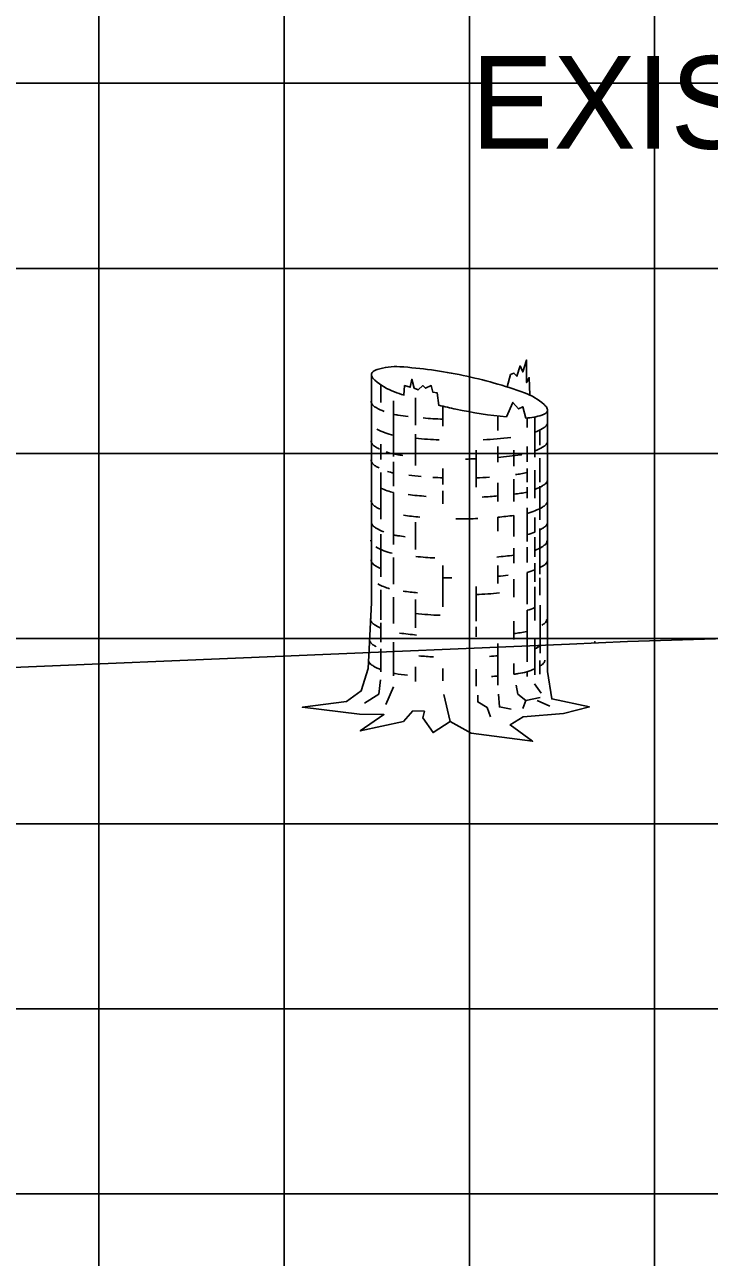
# Model space of a CAD drawing. Extents: x 1147190 to 1147360, y 608981 to 609091.
# Drawn here: x 1147223.54 to 1147227.24, y 609050.99 to 609057.65 of the extents above; entities that cross this region are included whole.
import ezdxf

# ---------------------------------------------------------------- set-up
doc = ezdxf.new("R2010")
doc.units = 0
for name, color, linetype in [('D_Text_Monospaced', 7, 'Continuous'), ('MAJOR', 7, 'Continuous'), ('MINOR', 7, 'Continuous'), ('S_Property_Well_GroundElevation', 7, 'Continuous'), ('S_Roadway_Centerline', 7, 'Continuous'), ('S_Trees_Decid_NonPay', 7, 'Continuous')]:
    doc.layers.add(name, color=color, linetype=linetype)

msp = doc.modelspace()

# ---------------------------------------------------------------- linework, layer by layer
at = {"layer": 'MAJOR'}
msp.add_line((1147202.9409, 609055.3351), (1147342.9409, 609055.3351), dxfattribs=at)
at = {"layer": 'MINOR'}
for p, q in [((1147223.9409, 609045.3351), (1147223.9409, 609065.3351)), ((1147224.9409, 609045.3351), (1147224.9409, 609065.3351)), ((1147225.9409, 609045.3351), (1147225.9409, 609065.3351)), ((1147226.9409, 609045.3351), (1147226.9409, 609065.3351)), ((1147202.9409, 609057.3351), (1147342.9409, 609057.3351)), ((1147202.9409, 609056.3351), (1147342.9409, 609056.3351)), ((1147202.9409, 609054.3351), (1147342.9409, 609054.3351)), ((1147202.9409, 609053.3351), (1147342.9409, 609053.3351)), ((1147202.9409, 609052.3351), (1147342.9409, 609052.3351)), ((1147202.9409, 609051.3351), (1147342.9409, 609051.3351))]:
    msp.add_line(p, q, dxfattribs=at)
at = {"layer": 'S_Property_Well_GroundElevation'}
for p, q in [((1147226.6173, 609054.3165), (1147226.6191, 609054.3183)), ((1147226.6173, 609054.3183), (1147226.6191, 609054.3165)), ((1147226.6182, 609054.3187), (1147226.6182, 609054.3161)), ((1147226.6169, 609054.3174), (1147226.6195, 609054.3174))]:
    msp.add_line(p, q, dxfattribs=at)
at = {"layer": 'S_Roadway_Centerline'}
msp.add_lwpolyline([(1147218.6881, 609053.9767), (1147226.4815, 609054.3046), (1147226.7946, 609054.3184), (1147244.6051, 609054.8887), (1147253.4336, 609054.3345), (1147254.6876, 609054.274), (1147257.845, 609055.0498), (1147258.3829, 609055.1775), (1147258.8229, 609055.1791), (1147261.2905, 609055.1012), (1147268.3857, 609055.2101), (1147272.5872, 609055.2789), (1147275.4381, 609055.2118), (1147283.4827, 609055.1294), (1147286.0369, 609055.041), (1147287.2734, 609054.9959), (1147292.8536, 609054.3763), (1147294.8648, 609054.203), (1147300.0193, 609054.043), (1147301.6888, 609053.9626), (1147303.1605, 609054.01), (1147308.9757, 609054.0188), (1147310.1526, 609054.0695), (1147311.9981, 609054.0658)], dxfattribs=at)
at = {"layer": 'S_Trees_Decid_NonPay'}
for p, q in [((1147225.4633, 609055.7053), (1147225.4633, 609055.6108)), ((1147225.5316, 609055.6186), (1147225.5316, 609055.3181)), ((1147225.6503, 609055.6357), (1147225.6503, 609055.4874)), ((1147225.7973, 609055.5898), (1147225.7973, 609055.4828)), ((1147226.0946, 609055.5373), (1147226.0946, 609055.4585)), ((1147226.252, 609055.5268), (1147226.252, 609055.4749)), ((1147226.2947, 609055.532), (1147226.2947, 609055.3142)), ((1147226.3216, 609055.4618), (1147226.3216, 609055.3798)), ((1147225.4633, 609055.3844), (1147225.4633, 609055.3017)), ((1147225.6503, 609055.4395), (1147225.6503, 609055.2709)), ((1147225.9771, 609055.3536), (1147225.9771, 609055.1534)), ((1147226.0946, 609055.3719), (1147226.0946, 609055.2873)), ((1147226.1812, 609055.3536), (1147226.1812, 609055.2669)), ((1147226.252, 609055.3719), (1147226.252, 609055.2892)), ((1147225.5316, 609055.2892), (1147225.5316, 609055.158)), ((1147225.7973, 609055.2545), (1147225.7973, 609055.1679)), ((1147226.252, 609055.2545), (1147226.252, 609055.1803)), ((1147226.3216, 609055.3102), (1147226.3216, 609055.1803)), ((1147225.4633, 609055.2322), (1147225.4633, 609054.9809)), ((1147226.1812, 609055.1967), (1147226.1812, 609055.0753)), ((1147226.2947, 609055.2453), (1147226.2947, 609055.0937)), ((1147225.5316, 609055.1239), (1147225.5316, 609054.8431)), ((1147225.7973, 609055.1331), (1147225.7973, 609055.0629)), ((1147226.0946, 609055.1764), (1147226.0946, 609055.0753)), ((1147226.252, 609055.1534), (1147226.252, 609055.0937)), ((1147226.3216, 609055.158), (1147226.3216, 609054.9763)), ((1147226.0946, 609054.9907), (1147226.0946, 609054.9146)), ((1147226.1812, 609054.9999), (1147226.1812, 609054.8857)), ((1147226.252, 609055.0406), (1147226.252, 609054.8595)), ((1147226.2947, 609054.9887), (1147226.2947, 609054.9106)), ((1147225.6503, 609054.9644), (1147225.6503, 609054.8162)), ((1147226.3216, 609054.929), (1147226.3216, 609054.6823)), ((1147225.4633, 609054.8982), (1147225.4633, 609054.6679)), ((1147226.2947, 609054.8837), (1147226.2947, 609054.7768)), ((1147226.1812, 609054.824), (1147226.1812, 609054.742)), ((1147226.252, 609054.828), (1147226.252, 609054.7459)), ((1147225.5316, 609054.7728), (1147225.5316, 609054.6285)), ((1147225.7973, 609054.7295), (1147225.7973, 609054.5071)), ((1147226.0946, 609054.7295), (1147226.0946, 609054.6324)), ((1147226.2947, 609054.742), (1147226.2947, 609054.641)), ((1147226.1812, 609054.6554), (1147226.1812, 609054.5583)), ((1147226.252, 609054.6921), (1147226.252, 609054.5215)), ((1147226.3216, 609054.6633), (1147226.3216, 609054.5688)), ((1147225.4633, 609054.5976), (1147225.4633, 609054.4369)), ((1147225.9771, 609054.616), (1147225.9771, 609054.429)), ((1147226.2947, 609054.6154), (1147226.2947, 609054.433)), ((1147225.5316, 609054.5583), (1147225.5316, 609054.4165)), ((1147225.6503, 609054.5465), (1147225.6503, 609054.3936)), ((1147226.252, 609054.4881), (1147226.252, 609054.2085)), ((1147226.3236, 609054.5156), (1147226.3222, 609054.2558)), ((1147225.4633, 609054.4205), (1147225.4633, 609054.3155)), ((1147225.9771, 609054.3982), (1147225.9771, 609054.345)), ((1147226.1812, 609054.429), (1147226.1812, 609054.3299)), ((1147226.2947, 609054.3299), (1147226.2947, 609054.1383)), ((1147225.4633, 609054.2788), (1147225.4633, 609054.1547)), ((1147225.5316, 609054.3155), (1147225.5316, 609054.1344)), ((1147226.0946, 609054.3076), (1147226.0946, 609054.0832)), ((1147226.1812, 609054.2007), (1147226.1812, 609054.1423)), ((1147226.3216, 609054.2171), (1147226.3216, 609054.1429)), ((1147225.6503, 609054.1816), (1147225.6503, 609054.1036)), ((1147225.7973, 609054.1738), (1147225.7973, 609054.1075)), ((1147225.9771, 609054.1692), (1147225.9771, 609054.0786)), ((1147226.252, 609054.156), (1147226.252, 609054.1305)), ((1147225.5309, 609054.0747), (1147225.4896, 609053.9782)), ((1147226.2927, 609054.0911), (1147226.3275, 609054.0399)), ((1147225.8373, 609053.8877), (1147225.8026, 609054.0333)), ((1147226.3747, 609053.9697), (1147226.3072, 609054.0005))]:
    msp.add_line(p, q, dxfattribs=at)
for points in [[(1147226.2678, 609055.6501), (1147226.2638, 609055.7446), (1147226.2494, 609055.7177), (1147226.2494, 609055.8391), (1147226.2284, 609055.7755), (1147226.214, 609055.8083), (1147226.1976, 609055.7525), (1147226.1812, 609055.7696), (1147226.1628, 609055.761), (1147226.1438, 609055.6941)], [(1147226.3629, 609055.5694), (1147226.3629, 609054.1574), (1147226.3852, 609054.0091), (1147226.5886, 609053.9658), (1147226.4489, 609053.9303), (1147226.2304, 609053.912), (1147226.1608, 609053.8686), (1147226.2822, 609053.7801), (1147225.9509, 609053.8234), (1147225.8373, 609053.8877), (1147225.7448, 609053.8273), (1147225.689, 609053.906), (1147225.6976, 609053.9428), (1147225.6359, 609053.9448), (1147225.5841, 609053.8877), (1147225.3518, 609053.8358), (1147225.4791, 609053.9244), (1147225.3472, 609053.9264), (1147225.0388, 609053.9638), (1147225.2776, 609053.9946), (1147225.3557, 609054.0524), (1147225.3944, 609054.1738), (1147225.4115, 609054.5274), (1147225.4115, 609055.761)], [(1147225.7757, 609055.595), (1147225.7671, 609055.662), (1147225.7429, 609055.6665), (1147225.7343, 609055.7013), (1147225.7035, 609055.6869), (1147225.689, 609055.7013), (1147225.6648, 609055.6784), (1147225.6418, 609055.6869), (1147225.6293, 609055.7361), (1147225.6215, 609055.6928), (1147225.5906, 609055.7013), (1147225.5873, 609055.6501)], [(1147226.2455, 609055.5261), (1147226.2284, 609055.5878), (1147226.2061, 609055.576), (1147226.1753, 609055.6108), (1147226.1418, 609055.5327)], [(1147225.4607, 609054.1121), (1147225.4522, 609054.0353), (1147225.3741, 609053.9861)], [(1147226.2448, 609054.0005), (1147226.2015, 609054.0353), (1147226.1936, 609054.0832)], [(1147225.9856, 609054.0294), (1147225.9856, 609053.9927), (1147226.0368, 609053.9618), (1147226.0539, 609053.912)], [(1147226.0972, 609054.0353), (1147226.1031, 609053.9658), (1147226.1667, 609053.9533)], [(1147226.3236, 609054.0169), (1147226.2448, 609054.0005), (1147226.2284, 609053.9572)]]:
    msp.add_lwpolyline(points, dxfattribs=at)
for centre, radius, start, end in [((1147225.4716, 609055.6996), 0.0935, 108.17229, 119.39599), ((1147225.5428, 609055.4827), 0.3218, 86.05435, 108.17229), ((1147225.3924, 609053.3027), 2.507, 78.17229, 86.05435), ((1147225.4297, 609055.7611), 0.0179, 168.17229, 184.22782), ((1147225.4355, 609055.7615), 0.0237, 184.22782, 198.17229), ((1147225.4297, 609055.7611), 0.0179, 152.11676, 168.17229), ((1147225.4449, 609055.7646), 0.0336, 198.17229, 216.94859), ((1147225.4348, 609055.7584), 0.0237, 138.17229, 152.11676), ((1147225.4422, 609055.7518), 0.0336, 119.39599, 138.17229), ((1147225.4927, 609055.8006), 0.0935, 216.9486, 228.17229), ((1147225.645, 609055.9708), 0.3218, 228.17229, 250.29024), ((1147225.3924, 609053.3027), 2.507, 70.29024, 78.17229), ((1147226.382, 609058.0279), 2.507, 250.29024, 251.52809), ((1147226.1294, 609055.3598), 0.3218, 48.17229, 70.29024), ((1147225.4301, 609055.6137), 0.0191, 163.94846, 180), ((1147225.4301, 609055.6137), 0.0191, 180, 196.05154), ((1147225.436, 609055.6154), 0.0252, 196.05154, 210), ((1147225.445, 609055.6206), 0.0356, 210, 228.74941), ((1147225.4864, 609055.6678), 0.0984, 228.74941, 240), ((1147226.382, 609058.0279), 2.507, 255.99867, 258.17229), ((1147226.2817, 609055.53), 0.0935, 36.9486, 48.17229), ((1147226.3295, 609055.566), 0.0336, 18.17229, 36.94859), ((1147225.6003, 609055.865), 0.3261, 240, 248.32432), ((1147225.6003, 609055.865), 0.3261, 257.8036, 261.8968), ((1147225.8864, 609057.875), 2.3564, 261.8968, 263.27991), ((1147225.8864, 609057.875), 2.3564, 265.24001, 267.83857), ((1147226.382, 609058.0279), 2.507, 258.17229, 264.50134), ((1147226.2316, 609055.8479), 0.3218, 272.44787, 288.17229), ((1147226.3028, 609055.631), 0.0935, 288.17229, 299.39599), ((1147226.3322, 609055.5788), 0.0336, 299.39599, 318.17229), ((1147226.3396, 609055.5722), 0.0237, 318.17229, 332.11676), ((1147226.3447, 609055.5695), 0.0179, 332.11676, 348.17229), ((1147226.3389, 609055.5691), 0.0237, 4.22782, 18.17229), ((1147226.3447, 609055.5695), 0.0179, 348.17229, 4.22783), ((1147225.6003, 609055.7518), 0.3261, 240.90989, 257.8036), ((1147226.1726, 609055.7518), 0.3261, 291.95057, 300), ((1147226.2865, 609055.5546), 0.0984, 300, 311.25059), ((1147226.3279, 609055.5074), 0.0356, 311.25059, 330), ((1147226.3369, 609055.5021), 0.0252, 330, 343.94846), ((1147226.3428, 609055.5004), 0.0191, 343.94846, 360), ((1147226.3428, 609055.5004), 0.0191, 360, 6.11276), ((1147225.4301, 609055.3996), 0.0191, 163.94846, 180), ((1147225.4301, 609055.3996), 0.0191, 180, 196.05154), ((1147225.436, 609055.4013), 0.0252, 196.05154, 210), ((1147225.445, 609055.4065), 0.0356, 210, 228.74941), ((1147225.8864, 609057.7618), 2.3564, 264.24201, 267.36728), ((1147225.8864, 609057.7618), 2.3564, 273.14807, 276.77338), ((1147226.3279, 609055.4065), 0.0356, 311.25059, 330), ((1147226.3369, 609055.4013), 0.0252, 330, 343.94846), ((1147226.3428, 609055.3996), 0.0191, 343.94846, 360), ((1147226.3428, 609055.3996), 0.0191, 360, 6.11276), ((1147225.4864, 609055.4537), 0.0984, 228.74941, 240), ((1147225.6003, 609055.6509), 0.3261, 240, 243.57187), ((1147225.6003, 609055.6509), 0.3261, 250.41675, 261.8968), ((1147225.8864, 609057.6609), 2.3564, 261.8968, 262.55191), ((1147225.8864, 609057.6609), 2.3564, 275.06468, 278.1032), ((1147226.1726, 609055.6509), 0.3261, 278.1032, 279.08543), ((1147226.1726, 609055.6509), 0.3261, 291.95057, 300), ((1147226.2865, 609055.4537), 0.0984, 300, 311.25059), ((1147225.4301, 609055.2966), 0.0191, 163.94846, 180), ((1147225.4301, 609055.2966), 0.0191, 180, 196.05154), ((1147225.436, 609055.2983), 0.0252, 196.05154, 210), ((1147225.445, 609055.3035), 0.0356, 210, 228.74941), ((1147225.4864, 609055.3507), 0.0984, 228.74941, 240), ((1147225.6003, 609055.5479), 0.3261, 240, 243.24303), ((1147225.8864, 609057.6609), 2.3564, 270.81188, 272.1981), ((1147226.3428, 609055.2966), 0.0191, 343.94846, 360), ((1147226.3428, 609055.2966), 0.0191, 360, 6.11276), ((1147225.6003, 609055.5479), 0.3261, 251.68306, 257.8036), ((1147225.8864, 609057.5579), 2.3564, 263.34129, 264.99462), ((1147225.8864, 609057.5579), 2.3564, 266.50356, 267.83857), ((1147225.8864, 609057.5579), 2.3564, 272.1981, 273.97408), ((1147225.8864, 609057.5579), 2.3564, 277.38384, 278.1032), ((1147226.1726, 609055.5479), 0.3261, 278.1032, 284.03823), ((1147226.3369, 609055.1933), 0.0252, 330, 343.94846), ((1147226.3428, 609055.1916), 0.0191, 343.94846, 360), ((1147226.3428, 609055.1916), 0.0191, 360, 6.11276), ((1147225.6003, 609055.4429), 0.3261, 245.15448, 257.8036), ((1147225.8864, 609057.4529), 2.3564, 277.18685, 278.1032), ((1147226.1726, 609055.4429), 0.3261, 278.1032, 284.03823), ((1147226.1726, 609055.4429), 0.3261, 291.95057, 300), ((1147226.2865, 609055.2457), 0.0984, 300, 311.25059), ((1147226.3279, 609055.1985), 0.0356, 311.25059, 330), ((1147225.4301, 609055.0766), 0.0191, 163.94846, 180), ((1147225.4301, 609055.0766), 0.0191, 180, 196.05154), ((1147225.436, 609055.0783), 0.0252, 196.05154, 210), ((1147225.445, 609055.0835), 0.0356, 210, 228.74941), ((1147225.4864, 609055.1307), 0.0984, 228.74941, 240), ((1147225.8864, 609057.4529), 2.3564, 263.26817, 265.63617), ((1147225.8864, 609057.4529), 2.3564, 273.0067, 275.06467), ((1147226.2865, 609055.1307), 0.0984, 300, 311.25059), ((1147226.3279, 609055.0835), 0.0356, 311.25059, 330), ((1147226.3369, 609055.0783), 0.0252, 330, 343.94846), ((1147226.3428, 609055.0766), 0.0191, 343.94846, 360), ((1147226.3428, 609055.0766), 0.0191, 360, 6.11276), ((1147225.6003, 609055.3279), 0.3261, 240, 245.15448), ((1147225.8864, 609057.3379), 2.3564, 262.65877, 264.79114), ((1147225.8864, 609057.3379), 2.3564, 275.06467, 277.18685), ((1147226.1726, 609055.3279), 0.3261, 284.03823, 300), ((1147225.4308, 609054.9622), 0.0191, 163.94846, 180), ((1147225.4308, 609054.9622), 0.0191, 180, 196.05154), ((1147225.4367, 609054.9639), 0.0252, 196.05154, 210), ((1147225.4458, 609054.9691), 0.0356, 210, 228.74941), ((1147225.4872, 609055.0163), 0.0984, 228.74941, 240), ((1147225.601, 609055.2135), 0.3261, 240, 247.86558), ((1147225.8864, 609057.3379), 2.3564, 269.55779, 270), ((1147225.8864, 609057.3379), 2.3564, 270, 272.414), ((1147226.1734, 609055.2135), 0.3261, 297.00583, 300), ((1147226.2872, 609055.0163), 0.0984, 300, 311.25059), ((1147226.3286, 609054.9691), 0.0356, 311.25059, 330), ((1147226.3377, 609054.9639), 0.0252, 330, 343.94846), ((1147226.3436, 609054.9622), 0.0191, 343.94846, 360), ((1147226.3436, 609054.9622), 0.0191, 0, 6.11277), ((1147225.4277, 609054.8619), 0.0191, 163.94846, 180), ((1147225.601, 609055.2135), 0.3261, 257.66994, 261.8968), ((1147225.8872, 609057.2235), 2.3564, 261.8968, 262.86151), ((1147226.1734, 609055.2135), 0.3261, 283.90364, 291.80982), ((1147226.3255, 609054.8688), 0.0356, 311.25059, 330), ((1147226.3345, 609054.8636), 0.0252, 330, 343.94846), ((1147226.3404, 609054.8619), 0.0191, 343.94846, 360), ((1147226.3404, 609054.8619), 0.0191, 0, 6.11277), ((1147225.5979, 609055.1132), 0.3261, 240, 256.90786), ((1147225.8841, 609057.1232), 2.3564, 274.97344, 277.24554), ((1147226.1702, 609055.1132), 0.3261, 292.40493, 300), ((1147226.2841, 609054.916), 0.0984, 300, 311.25059), ((1147225.4301, 609054.7572), 0.0191, 163.94846, 180), ((1147225.4301, 609054.7572), 0.0191, 180, 196.05154), ((1147225.436, 609054.7589), 0.0252, 196.05154, 210), ((1147225.445, 609054.7641), 0.0356, 210, 228.74941), ((1147225.4864, 609054.8113), 0.0984, 228.74941, 240), ((1147225.6003, 609055.0085), 0.3261, 240, 245.15448), ((1147225.8841, 609057.1232), 2.3564, 264.3443, 266.85288), ((1147226.1726, 609055.0085), 0.3261, 297.15252, 300), ((1147226.2865, 609054.8113), 0.0984, 300, 311.25059), ((1147226.3279, 609054.7641), 0.0356, 311.25059, 330), ((1147226.3369, 609054.7589), 0.0252, 330, 343.94846), ((1147226.3428, 609054.7572), 0.0191, 343.94846, 360), ((1147226.3428, 609054.7572), 0.0191, 360, 6.11276), ((1147225.8864, 609057.0185), 2.3564, 267.83857, 269.00542), ((1147225.8864, 609057.0185), 2.3564, 275.06467, 276.42799), ((1147226.1726, 609055.0085), 0.3261, 284.03823, 291.95057), ((1147226.3428, 609054.6666), 0.0191, 360, 6.11276), ((1147225.6003, 609054.9179), 0.3261, 241.93896, 253.9183), ((1147225.8864, 609056.9279), 2.3564, 262.58433, 264.48651), ((1147225.8864, 609056.9279), 2.3564, 272.1981, 275.27259), ((1147225.8864, 609056.8147), 2.3564, 264.24201, 267.46903), ((1147226.1726, 609054.8046), 0.3261, 284.03823, 291.95057), ((1147225.426, 609054.4381), 0.0191, 163.94846, 180), ((1147225.426, 609054.4381), 0.0191, 180, 196.05154), ((1147225.4319, 609054.4398), 0.0252, 196.05154, 210), ((1147225.441, 609054.445), 0.0356, 210, 228.74941), ((1147225.4824, 609054.4922), 0.0984, 228.74941, 240), ((1147225.5962, 609054.6894), 0.3261, 240, 245.93749), ((1147226.2824, 609054.4922), 0.0984, 300, 311.25059), ((1147226.3238, 609054.445), 0.0356, 311.25059, 330), ((1147226.3329, 609054.4398), 0.0252, 330, 343.94846), ((1147226.3388, 609054.4381), 0.0191, 343.94846, 360), ((1147226.3388, 609054.4381), 0.0191, 360, 6.11276), ((1147225.4211, 609054.3275), 0.0191, 163.94846, 180), ((1147225.4211, 609054.3275), 0.0191, 180, 196.05154), ((1147225.427, 609054.3292), 0.0252, 196.05154, 210), ((1147225.8824, 609056.6994), 2.3564, 262.22258, 264.4852), ((1147225.8824, 609056.6994), 2.3564, 277.28629, 278.1032), ((1147226.1686, 609054.6894), 0.3261, 278.1032, 284.77414), ((1147225.4361, 609054.3344), 0.0356, 210, 228.74941), ((1147225.4775, 609054.3816), 0.0984, 228.74941, 240), ((1147225.5913, 609054.5788), 0.3261, 240, 241.90969), ((1147226.1637, 609054.5788), 0.3261, 293.6544, 300), ((1147225.4157, 609054.2172), 0.0191, 163.94846, 180), ((1147225.4157, 609054.2172), 0.0191, 180, 196.05154), ((1147225.4216, 609054.2189), 0.0252, 196.05154, 210), ((1147225.4306, 609054.2242), 0.0356, 210, 228.74941), ((1147225.472, 609054.2714), 0.0984, 228.74941, 240), ((1147225.5858, 609054.4685), 0.3261, 240, 247.9161), ((1147225.8775, 609056.5888), 2.3564, 264.90887, 266.81578), ((1147225.8775, 609056.5888), 2.3564, 274.18643, 275.28293), ((1147226.2721, 609054.2714), 0.0984, 300, 311.25059), ((1147226.3135, 609054.2242), 0.0356, 311.25059, 330), ((1147226.3225, 609054.2189), 0.0252, 330, 343.94846), ((1147226.3284, 609054.2172), 0.0191, 343.94846, 360), ((1147226.3284, 609054.2172), 0.0191, 0, 6.11277), ((1147225.5858, 609054.4685), 0.3261, 260.38342, 261.8968), ((1147225.872, 609056.4786), 2.3564, 261.8968, 263.53328), ((1147225.872, 609056.4786), 2.3564, 274.55512, 275.4167), ((1147225.872, 609056.4786), 2.3564, 277.54032, 278.1032), ((1147226.1582, 609054.4685), 0.3261, 278.1032, 294.70938)]:
    msp.add_arc(centre, radius, start, end, dxfattribs=at)

# ---------------------------------------------------------------- texts
at = {"layer": 'D_Text_Monospaced'}
msp.add_text('EXIST. 4",APPLE,,', height=0.49998, dxfattribs=at).set_placement((1147225.9482, 609056.9814))
at = {"layer": 'S_Property_Well_GroundElevation'}
msp.add_text('WG', height=0.00583, dxfattribs=at).set_placement((1147226.6139, 609054.309))

doc.saveas('drawing.dxf')
